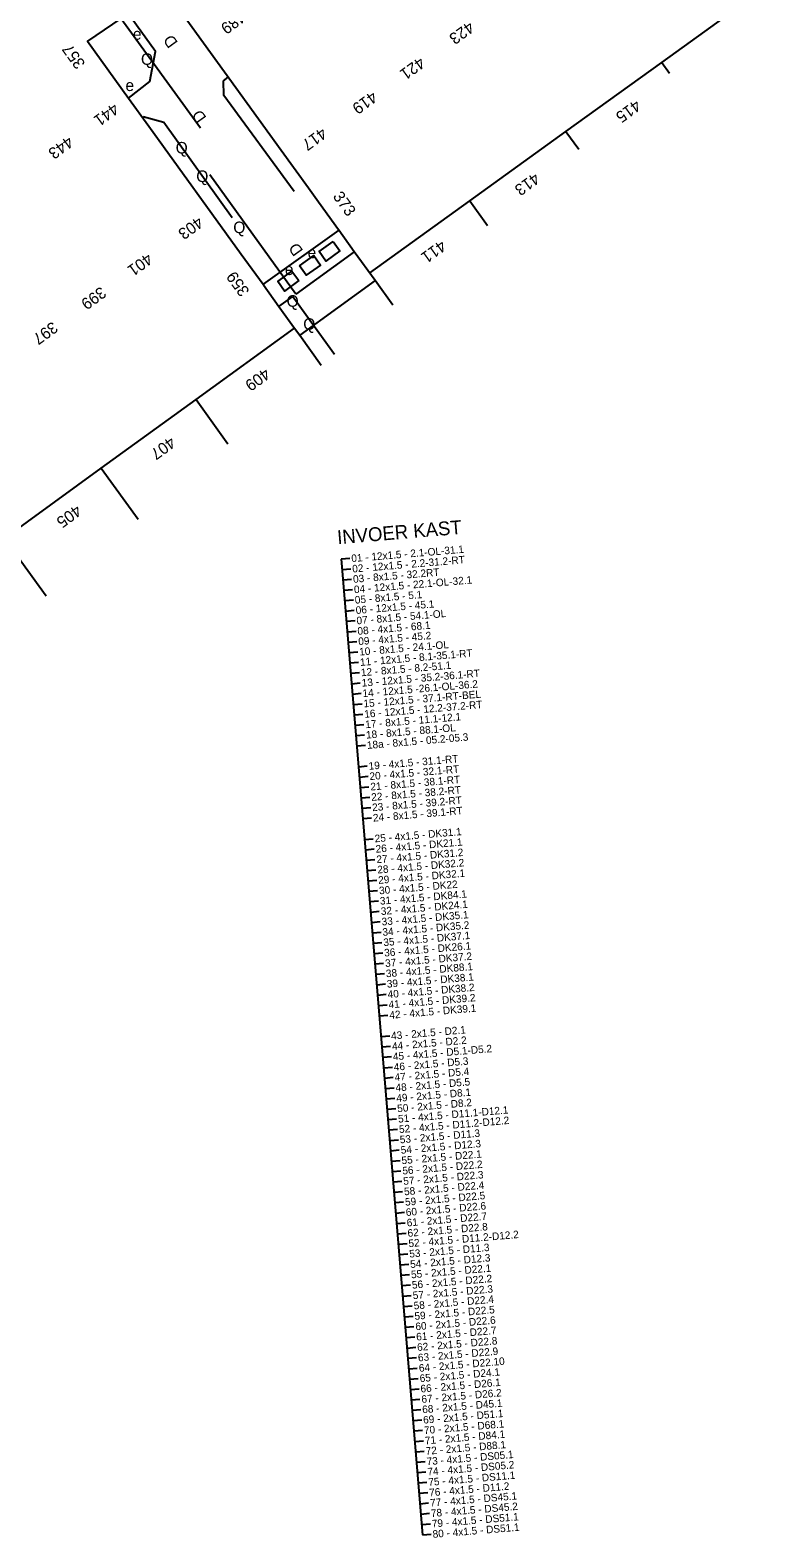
# Model space of a CAD drawing. Extents: x 81617 to 82144, y 454649 to 455150.
# Drawn here: x 81949.9 to 82012.9, y 454762.6 to 454892.9 of the extents above; entities that cross this region are included whole.
import ezdxf

# ---------------------------------------------------------------- set-up
doc = ezdxf.new("R2010")
doc.units = 0
doc.layers.add('B-WE-OG-TOPOGRAFIE-G', color=7, linetype='Continuous')
doc.layers.add('N-OI-KL-VRI_KABELGEUL-T18', color=7, linetype='Continuous')

msp = doc.modelspace()

# ---------------------------------------------------------------- linework, layer by layer
at = {"layer": 'B-WE-OG-TOPOGRAFIE-G'}
for p, q in [((82004.5, 454890.06), (82012.9, 454896.12)), ((81964.63, 454884.37), (81957.74, 454893.85)), ((81996.21, 454884.09), (82004.5, 454890.06)), ((82004.5, 454890.06), (82005.16, 454889.14)), ((81966.62, 454888.48), (81967.02, 454888.8)), ((81966.65, 454887.21), (81966.62, 454888.48)), ((81958.41, 454886.97), (81960.16, 454884.55)), ((81972.73, 454878.92), (81966.65, 454887.21)), ((81959.68, 454885.39), (81961.45, 454884.9)), ((81961.45, 454884.9), (81967.37, 454876.65)), ((81987.91, 454878.1), (81996.21, 454884.09)), ((81996.21, 454884.09), (81997.32, 454882.56)), ((81972.86, 454870.05), (81965.44, 454880.34)), ((81979.25, 454871.86), (81987.91, 454878.1)), ((81987.91, 454878.1), (81989.45, 454875.96)), ((81976.58, 454875.56), (81970.03, 454870.89)), ((81977.92, 454873.7), (81976.58, 454875.56)), ((81977.92, 454873.7), (81972.86, 454870.05)), ((81979.72, 454871.21), (81977.92, 454873.7)), ((81979.72, 454871.21), (81973.2, 454866.5)), ((81981.26, 454869.08), (81979.72, 454871.21)), ((81971.41, 454868.97), (81972.62, 454869.85)), ((81971.41, 454868.97), (81972.75, 454867.11)), ((81964.24, 454860.94), (81972.75, 454867.11)), ((81972.75, 454867.11), (81973.2, 454866.5)), ((81973.2, 454866.5), (81975.07, 454863.9)), ((81956.04, 454855), (81964.24, 454860.94)), ((81964.24, 454860.94), (81967, 454857.12)), ((81947.64, 454848.91), (81956.04, 454855)), ((81956.04, 454855), (81959.23, 454850.6))]:
    msp.add_line(p, q, dxfattribs=at)
for points in [[(81958.41, 454886.97), (81960.25, 454888.42), (81960.74, 454891.01), (81949.99, 454905.93), (81952.52, 454907.79)], [(81976.58, 454875.56), (81976.56, 454875.59), (81974.83, 454877.98), (81973.95, 454879.2), (81971.61, 454882.44), (81966.71, 454889.23), (81961.49, 454896.45)], [(81957.74, 454893.85), (81954.86, 454891.9), (81958.41, 454886.97)], [(81960.16, 454884.55), (81968.14, 454873.5), (81970.03, 454870.89)], [(81976.1, 454874.59), (81976.68, 454873.77), (81975.46, 454872.9), (81974.88, 454873.72), (81976.1, 454874.59)], [(81973.18, 454872.5), (81974.41, 454873.38), (81975, 454872.54), (81973.76, 454871.68), (81973.18, 454872.5)], [(81951.29, 454843.93), (81946.86, 454849.98), (81944.72, 454852.91), (81938.62, 454861.25), (81938.47, 454861.46), (81936.62, 454863.98), (81930.65, 454872.14), (81929.05, 454870.82)], [(81973.12, 454871.21), (81971.89, 454870.31), (81971.3, 454871.14), (81972.53, 454872.03), (81973.12, 454871.21)], [(81970.03, 454870.89), (81970.06, 454870.84), (81971.41, 454868.97)], [(81972.62, 454869.85), (81976.2, 454864.84)]]:
    msp.add_lwpolyline(points, dxfattribs=at)
at = {"layer": 'N-OI-KL-VRI_KABELGEUL-T18'}
for p, q in [((81977.54, 454847.21), (81976.79, 454847.15)), ((81976.79, 454847.15), (81983.82, 454762.84)), ((81976.87, 454846.25), (81977.62, 454846.31)), ((81976.94, 454845.35), (81977.69, 454845.42)), ((81977.02, 454844.46), (81977.77, 454844.52)), ((81977.09, 454843.56), (81977.84, 454843.62)), ((81977.17, 454842.66), (81977.92, 454842.73)), ((81977.24, 454841.77), (81977.99, 454841.83)), ((81977.32, 454840.87), (81978.07, 454840.93)), ((81977.39, 454839.97), (81978.14, 454840.03)), ((81977.47, 454839.08), (81978.22, 454839.14)), ((81977.54, 454838.18), (81978.29, 454838.24)), ((81977.62, 454837.28), (81978.36, 454837.34)), ((81977.69, 454836.38), (81978.44, 454836.45)), ((81977.77, 454835.49), (81978.51, 454835.55)), ((81977.84, 454834.59), (81978.59, 454834.65)), ((81977.92, 454833.69), (81978.66, 454833.76)), ((81977.99, 454832.8), (81978.74, 454832.86)), ((81978.07, 454831.9), (81978.81, 454831.96)), ((81978.14, 454831), (81978.89, 454831.07)), ((81978.29, 454829.21), (81979.04, 454829.27)), ((81978.37, 454828.31), (81979.11, 454828.38)), ((81978.44, 454827.42), (81979.19, 454827.48)), ((81978.51, 454826.52), (81979.26, 454826.58)), ((81978.59, 454825.62), (81979.34, 454825.68)), ((81978.66, 454824.73), (81979.41, 454824.79)), ((81978.81, 454822.93), (81979.56, 454822.99)), ((81978.89, 454822.03), (81979.64, 454822.1)), ((81978.96, 454821.14), (81979.71, 454821.2)), ((81979.04, 454820.24), (81979.79, 454820.3)), ((81979.11, 454819.34), (81979.86, 454819.41)), ((81979.19, 454818.45), (81979.94, 454818.51)), ((81979.26, 454817.55), (81980.01, 454817.61)), ((81979.34, 454816.65), (81980.08, 454816.72)), ((81979.41, 454815.76), (81980.16, 454815.82)), ((81979.49, 454814.86), (81980.23, 454814.92)), ((81979.56, 454813.96), (81980.31, 454814.02)), ((81979.64, 454813.07), (81980.38, 454813.13)), ((81979.71, 454812.17), (81980.46, 454812.23)), ((81979.79, 454811.27), (81980.53, 454811.33)), ((81979.86, 454810.37), (81980.61, 454810.44)), ((81979.94, 454809.48), (81980.68, 454809.54)), ((81980.01, 454808.58), (81980.76, 454808.64)), ((81980.09, 454807.68), (81980.83, 454807.75)), ((81980.23, 454805.89), (81980.98, 454805.95)), ((81980.31, 454804.99), (81981.06, 454805.06)), ((81980.38, 454804.1), (81981.13, 454804.16)), ((81980.46, 454803.2), (81981.21, 454803.26)), ((81980.53, 454802.3), (81981.28, 454802.37)), ((81980.61, 454801.41), (81981.36, 454801.47)), ((81980.68, 454800.51), (81981.43, 454800.57)), ((81980.76, 454799.61), (81981.51, 454799.67)), ((81980.83, 454798.72), (81981.58, 454798.78)), ((81980.91, 454797.82), (81981.66, 454797.88)), ((81980.98, 454796.92), (81981.73, 454796.98)), ((81981.06, 454796.02), (81981.8, 454796.09)), ((81981.13, 454795.13), (81981.88, 454795.19)), ((81981.21, 454794.23), (81981.95, 454794.29)), ((81981.28, 454793.33), (81982.03, 454793.4)), ((81981.36, 454792.44), (81982.1, 454792.5)), ((81981.43, 454791.54), (81982.18, 454791.6)), ((81981.51, 454790.64), (81982.25, 454790.71)), ((81981.58, 454789.75), (81982.33, 454789.81)), ((81981.66, 454788.85), (81982.4, 454788.91)), ((81981.73, 454787.95), (81982.48, 454788.02)), ((81981.81, 454787.06), (81982.55, 454787.12)), ((81981.88, 454786.16), (81982.63, 454786.22)), ((81981.95, 454785.26), (81982.7, 454785.32)), ((81982.03, 454784.37), (81982.78, 454784.43)), ((81982.1, 454783.47), (81982.85, 454783.53)), ((81982.18, 454782.57), (81982.93, 454782.63)), ((81982.25, 454781.67), (81983, 454781.74)), ((81982.33, 454780.78), (81983.08, 454780.84)), ((81982.4, 454779.88), (81983.15, 454779.94)), ((81982.48, 454778.98), (81983.23, 454779.05)), ((81982.55, 454778.09), (81983.3, 454778.15)), ((81982.63, 454777.19), (81983.37, 454777.25)), ((81982.7, 454776.29), (81983.45, 454776.36)), ((81982.78, 454775.4), (81983.52, 454775.46)), ((81982.85, 454774.5), (81983.6, 454774.56)), ((81982.93, 454773.6), (81983.67, 454773.66)), ((81983, 454772.71), (81983.75, 454772.77)), ((81983.08, 454771.81), (81983.82, 454771.87)), ((81983.15, 454770.91), (81983.9, 454770.97)), ((81983.23, 454770.02), (81983.97, 454770.08)), ((81983.3, 454769.12), (81984.05, 454769.18)), ((81983.38, 454768.22), (81984.12, 454768.28)), ((81983.45, 454767.32), (81984.2, 454767.39)), ((81983.52, 454766.43), (81984.27, 454766.49)), ((81983.6, 454765.53), (81984.35, 454765.59)), ((81983.67, 454764.63), (81984.42, 454764.7)), ((81983.75, 454763.74), (81984.5, 454763.8)), ((81983.82, 454762.84), (81984.57, 454762.9))]:
    msp.add_line(p, q, dxfattribs=at)

# ---------------------------------------------------------------- texts
at = {"layer": 'B-WE-OG-TOPOGRAFIE-G'}
for s, rotation, p in [('489', 215.8154, (81968.09, 454894.55)), ('423', 215.7403, (81987.84, 454893.66)), ('D', 125.8399, (81962.71, 454891.78)), ('357', 125.8334, (81954.71, 454889.96)), ('421', 215.7403, (81983.58, 454890.59)), ('419', 215.7403, (81979.46, 454887.63)), ('415', 215.7885, (82002.24, 454886.89)), ('441', 215.9791, (81957.11, 454886.6)), ('D', 125.8292, (81965.18, 454885.29)), ('417', 215.7403, (81975.1, 454884.49)), ('443', 215.9791, (81953.18, 454883.75)), ('413', 215.7885, (81993.5, 454880.59)), ('373', 305.8335, (81976.02, 454878.48)), ('403', 215.8412, (81964.41, 454876.8)), ('D', 125.8384, (81973.54, 454873.8)), ('411', 215.7885, (81985.41, 454874.76)), ('401', 215.8412, (81960.03, 454873.64)), ('359', 125.8334, (81968.91, 454870.3)), ('399', 215.8412, (81956.01, 454870.74)), ('397', 215.8412, (81951.83, 454867.72)), ('409', 215.9422, (81970.19, 454863.71)), ('407', 215.9422, (81962.01, 454857.78)), ('405', 215.9422, (81953.88, 454851.89))]:
    msp.add_text(s, height=1, rotation=rotation, dxfattribs=at).set_placement(p)
for s, p in [('e', (81958.78, 454892.02)), ('Q', (81959.48, 454889.85)), ('e', (81958.14, 454887.59)), ('Q', (81962.48, 454882.19)), ('Q', (81964.26, 454879.73)), ('Q', (81967.46, 454875.31)), ('e', (81973.89, 454873.14)), ('e', (81971.92, 454871.69)), ('Q', (81972.07, 454868.95)), ('Q', (81973.51, 454866.96))]:
    msp.add_text(s, height=1, dxfattribs=at).set_placement(p)
at = {"layer": 'N-OI-KL-VRI_KABELGEUL-T18'}
for s, height, p in [('INVOER KAST', 1.2, (81976.49, 454848.43)), ('01 - 12x1.5 - 2.1-OL-31.1', 0.65, (81977.69, 454846.88)), ('02 - 12x1.5 - 2.2-31.2-RT', 0.65, (81977.77, 454845.98)), ('03 - 8x1.5 - 32.2RT', 0.65, (81977.84, 454845.09)), ('04 - 12x1.5 - 22.1-OL-32.1', 0.65, (81977.92, 454844.19)), ('05 - 8x1.5 - 5.1', 0.65, (81977.99, 454843.29)), ('06 - 12x1.5 - 45.1', 0.65, (81978.07, 454842.4)), ('07 - 8x1.5 - 54.1-OL', 0.65, (81978.14, 454841.5)), ('08 - 4x1.5 - 68.1', 0.65, (81978.22, 454840.6)), ('09 - 4x1.5 - 45.2', 0.65, (81978.29, 454839.71)), ('10 - 8x1.5 - 24.1-OL', 0.65, (81978.37, 454838.81)), ('11 - 12x1.5 - 8.1-35.1-RT', 0.65, (81978.44, 454837.91)), ('12 - 8x1.5 - 8.2-51.1', 0.65, (81978.52, 454837.02)), ('13 - 12x1.5 - 35.2-36.1-RT', 0.65, (81978.59, 454836.12)), ('14 - 12x1.5 -26.1-OL-36.2', 0.65, (81978.66, 454835.22)), ('15 - 12x1.5 - 37.1-RT-BEL', 0.65, (81978.74, 454834.33)), ('16 - 12x1.5 - 12.2-37.2-RT', 0.65, (81978.81, 454833.43)), ('17 - 8x1.5 - 11.1-12.1', 0.65, (81978.89, 454832.53)), ('18 - 8x1.5 - 88.1-OL', 0.65, (81978.96, 454831.63)), ('18a - 8x1.5 - 05.2-05.3', 0.65, (81979.04, 454830.74)), ('19 - 4x1.5 - 31.1-RT', 0.65, (81979.19, 454828.94)), ('20 - 4x1.5 - 32.1-RT', 0.65, (81979.26, 454828.05)), ('21 - 8x1.5 - 38.1-RT', 0.65, (81979.34, 454827.15)), ('22 - 8x1.5 - 38.2-RT', 0.65, (81979.41, 454826.25)), ('23 - 8x1.5 - 39.2-RT', 0.65, (81979.49, 454825.36)), ('24 - 8x1.5 - 39.1-RT', 0.65, (81979.56, 454824.46)), ('25 - 4x1.5 - DK31.1', 0.65, (81979.71, 454822.67)), ('26 - 4x1.5 - DK21.1', 0.65, (81979.79, 454821.77)), ('27 - 4x1.5 - DK31.2', 0.65, (81979.86, 454820.87)), ('28 - 4x1.5 - DK32.2', 0.65, (81979.94, 454819.98)), ('29 - 4x1.5 - DK32.1', 0.65, (81980.01, 454819.08)), ('30 - 4x1.5 - DK22', 0.65, (81980.09, 454818.18)), ('31 - 4x1.5 - DK84.1', 0.65, (81980.16, 454817.28)), ('32 - 4x1.5 - DK24.1', 0.65, (81980.24, 454816.39)), ('33 - 4x1.5 - DK35.1', 0.65, (81980.31, 454815.49)), ('34 - 4x1.5 - DK35.2', 0.65, (81980.38, 454814.59)), ('35 - 4x1.5 - DK37.1', 0.65, (81980.46, 454813.7)), ('36 - 4x1.5 - DK26.1', 0.65, (81980.53, 454812.8)), ('37 - 4x1.5 - DK37.2', 0.65, (81980.61, 454811.9)), ('38 - 4x1.5 - DK88.1', 0.65, (81980.68, 454811.01)), ('39 - 4x1.5 - DK38.1', 0.65, (81980.76, 454810.11)), ('40 - 4x1.5 - DK38.2', 0.65, (81980.83, 454809.21)), ('41 - 4x1.5 - DK39.2', 0.65, (81980.91, 454808.32)), ('42 - 4x1.5 - DK39.1', 0.65, (81980.98, 454807.42)), ('43 - 2x1.5 - D2.1', 0.65, (81981.13, 454805.63)), ('44 - 2x1.5 - D2.2', 0.65, (81981.21, 454804.73)), ('45 - 4x1.5 - D5.1-D5.2', 0.65, (81981.28, 454803.83)), ('46 - 2x1.5 - D5.3', 0.65, (81981.36, 454802.93)), ('47 - 2x1.5 - D5.4', 0.65, (81981.43, 454802.04)), ('48 - 2x1.5 - D5.5', 0.65, (81981.51, 454801.14)), ('49 - 2x1.5 - D8.1', 0.65, (81981.58, 454800.24)), ('50 - 2x1.5 - D8.2', 0.65, (81981.66, 454799.35)), ('51 - 4x1.5 - D11.1-D12.1', 0.65, (81981.73, 454798.45)), ('52 - 4x1.5 - D11.2-D12.2', 0.65, (81981.81, 454797.55)), ('53 - 2x1.5 - D11.3', 0.65, (81981.88, 454796.66)), ('54 - 2x1.5 - D12.3', 0.65, (81981.96, 454795.76)), ('55 - 2x1.5 - D22.1', 0.65, (81982.03, 454794.86)), ('56 - 2x1.5 - D22.2', 0.65, (81982.1, 454793.97)), ('57 - 2x1.5 - D22.3', 0.65, (81982.18, 454793.07)), ('58 - 2x1.5 - D22.4', 0.65, (81982.25, 454792.17)), ('59 - 2x1.5 - D22.5', 0.65, (81982.33, 454791.27)), ('60 - 2x1.5 - D22.6', 0.65, (81982.4, 454790.38)), ('61 - 2x1.5 - D22.7', 0.65, (81982.48, 454789.48)), ('62 - 2x1.5 - D22.8', 0.65, (81982.55, 454788.58)), ('52 - 4x1.5 - D11.2-D12.2', 0.65, (81982.63, 454787.69)), ('53 - 2x1.5 - D11.3', 0.65, (81982.7, 454786.79)), ('54 - 2x1.5 - D12.3', 0.65, (81982.78, 454785.89)), ('55 - 2x1.5 - D22.1', 0.65, (81982.85, 454785)), ('56 - 2x1.5 - D22.2', 0.65, (81982.93, 454784.1)), ('57 - 2x1.5 - D22.3', 0.65, (81983, 454783.2)), ('58 - 2x1.5 - D22.4', 0.65, (81983.08, 454782.31)), ('59 - 2x1.5 - D22.5', 0.65, (81983.15, 454781.41)), ('60 - 2x1.5 - D22.6', 0.65, (81983.23, 454780.51)), ('61 - 2x1.5 - D22.7', 0.65, (81983.3, 454779.62)), ('62 - 2x1.5 - D22.8', 0.65, (81983.38, 454778.72)), ('63 - 2x1.5 - D22.9', 0.65, (81983.45, 454777.82)), ('64 - 2x1.5 - D22.10', 0.65, (81983.53, 454776.92)), ('65 - 2x1.5 - D24.1', 0.65, (81983.6, 454776.03)), ('66 - 2x1.5 - D26.1', 0.65, (81983.67, 454775.13)), ('67 - 2x1.5 - D26.2', 0.65, (81983.75, 454774.23)), ('68 - 2x1.5 - D45.1', 0.65, (81983.82, 454773.34)), ('69 - 2x1.5 - D51.1', 0.65, (81983.9, 454772.44)), ('70 - 2x1.5 - D68.1', 0.65, (81983.97, 454771.54)), ('71 - 2x1.5 - D84.1', 0.65, (81984.05, 454770.65)), ('72 - 2x1.5 - D88.1', 0.65, (81984.12, 454769.75)), ('73 - 4x1.5 - DS05.1', 0.65, (81984.2, 454768.85)), ('74 - 4x1.5 - DS05.2', 0.65, (81984.27, 454767.96)), ('75 - 4x1.5 - DS11.1', 0.65, (81984.35, 454767.06)), ('76 - 4x1.5 - D11.2', 0.65, (81984.42, 454766.16)), ('77 - 4x1.5 - DS45.1', 0.65, (81984.5, 454765.27)), ('78 - 4x1.5 - DS45.2', 0.65, (81984.57, 454764.37)), ('79 - 4x1.5 - DS51.1', 0.65, (81984.65, 454763.47)), ('80 - 4x1.5 - DS51.1', 0.65, (81984.72, 454762.57))]:
    msp.add_text(s, height=height, rotation=4.766, dxfattribs=at).set_placement(p)

doc.saveas('drawing.dxf')
